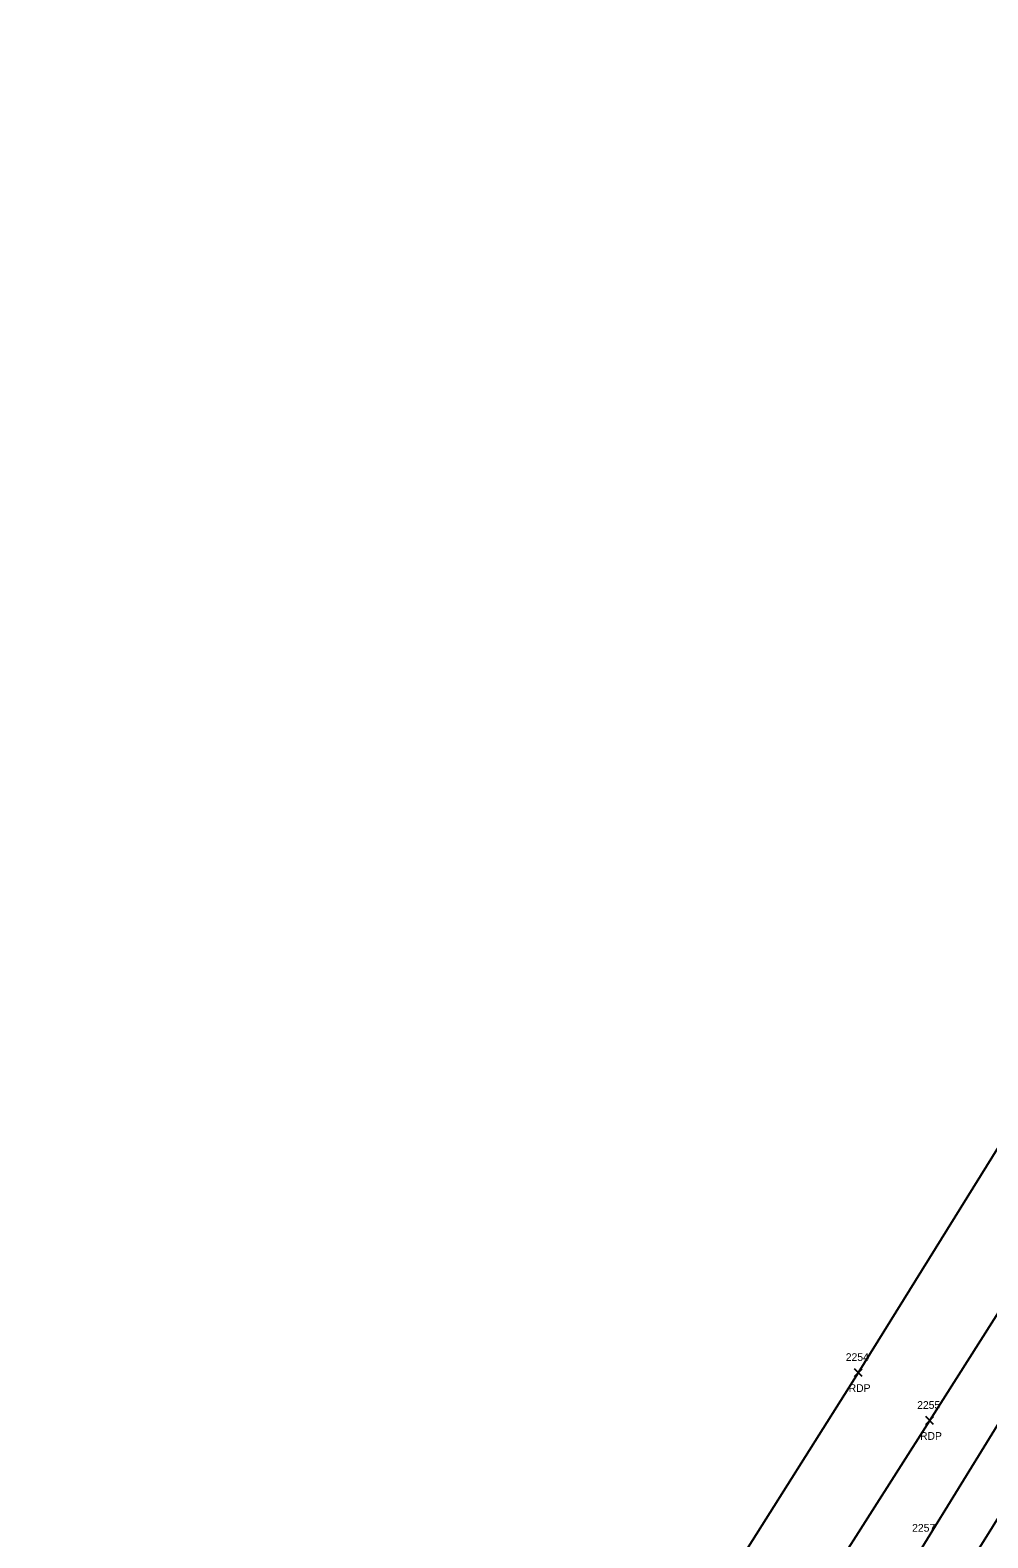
# Model space of a CAD drawing. Extents: x 1508122 to 1515053, y 865012 to 875267.
# Drawn here: x 1513481 to 1513728.5, y 873540.6 to 873930.3 of the extents above; entities that cross this region are included whole.
import ezdxf

# ---------------------------------------------------------------- set-up
doc = ezdxf.new("R2010")
doc.units = 0
for name, color, linetype in [('L_I', 7, 'Continuous'), ('LFNC', 7, 'Continuous'), ('P_A', 7, 'Continuous'), ('P_I', 7, 'Continuous'), ('P_TIC', 7, 'Continuous'), ('PET', 7, 'Continuous'), ('RRB', 7, 'Continuous')]:
    doc.layers.add(name, color=color, linetype=linetype)

msp = doc.modelspace()

# ---------------------------------------------------------------- linework, layer by layer
at = {"layer": 'LFNC'}
msp.add_lwpolyline([(1513218.01, 872682.67), (1513239.79, 872733.41), (1513260.59, 872779.32), (1513279.8, 872820.34), (1513309.34, 872879.26), (1513337.46, 872931.88), (1513364.68, 872976.76), (1513384.37, 873008.89), (1513425.94, 873076.78), (1513474.35, 873155.62), (1513492.34, 873185.42), (1513532.61, 873250.79), (1513565.82, 873304.9), (1513599.41, 873358.19), (1513608.93, 873372.42), (1513641.55, 873425.64), (1513687.17, 873499.06), (1513712.19, 873539.19), (1513738.32, 873581.58), (1513785.03, 873656.05), (1513811.88, 873700.06), (1513821.63, 873694.46)], dxfattribs=at)
at = {"layer": 'P_TIC'}
for points in [[(1513694.04, 873582.32), (1513696.04, 873584.32)], [(1513696.04, 873582.32), (1513694.04, 873584.32)], [(1513712.49, 873569.94), (1513714.49, 873571.94)], [(1513714.49, 873569.94), (1513712.49, 873571.94)]]:
    msp.add_lwpolyline(points, dxfattribs=at)
at = {"layer": 'PET'}
for points in [[(1513466.17, 873213.07), (1513500.31, 873271.08), (1513533.51, 873325.85), (1513565.92, 873377.51), (1513601.02, 873434.43), (1513630.8, 873481.59), (1513663.12, 873532.69), (1513695.04, 873583.32), (1513791.03, 873737.88), (1513811.04, 873770.52), (1513826.41, 873795.21), (1513862.7, 873855.82), (1513892.11, 873904.49), (1513923.1, 873954.81)], [(1513455.04, 873151.27), (1513485.29, 873202.33), (1513519.6, 873259.87), (1513551.9, 873312.77), (1513584.37, 873365.63), (1513617.09, 873418.81), (1513648.76, 873468.83), (1513681.49, 873520.59), (1513713.49, 873570.94), (1513800.66, 873708.29), (1513826.54, 873751.18), (1513852.76, 873793.88), (1513881.72, 873842.17), (1513911.67, 873891.89), (1513942.82, 873942.89)]]:
    msp.add_lwpolyline(points, dxfattribs=at)
at = {"layer": 'RRB'}
msp.add_lwpolyline([(1513228.31, 872677.99), (1513247.91, 872725.05), (1513270.86, 872775.34), (1513289.12, 872813.81), (1513319.1, 872873.87), (1513347.47, 872925.52), (1513374.77, 872971.44), (1513393.49, 873000.11), (1513437.27, 873071.02), (1513458.13, 873103.89), (1513504.32, 873179.38), (1513525.85, 873213.8), (1513574, 873293.73), (1513619.17, 873366.93), (1513650.95, 873417.63), (1513697.43, 873492.91), (1513723.07, 873532.74), (1513749.97, 873575.84), (1513797.76, 873652.14), (1513828.99, 873702.68), (1513841.18, 873722.67), (1513905.39, 873826.67), (1513957.69, 873911.9), (1513997.47, 873975.73)], dxfattribs=at)

# ---------------------------------------------------------------- texts
at = {"layer": 'L_I'}
msp.add_text('2257', height=2, dxfattribs=at).set_placement((1513708.93, 873542.19))
at = {"layer": 'P_A'}
for p in [(1513692.53, 873578.32), (1513710.97, 873565.94)]:
    msp.add_text('RDP', height=2, dxfattribs=at).set_placement(p)
at = {"layer": 'P_I'}
for s, p in [('2254', (1513691.78, 873586.32)), ('2255', (1513710.23, 873573.94))]:
    msp.add_text(s, height=2, dxfattribs=at).set_placement(p)

doc.saveas('drawing.dxf')
